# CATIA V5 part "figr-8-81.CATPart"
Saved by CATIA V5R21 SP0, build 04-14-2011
Part number: Part1
Bounding box of the stored display mesh (mm): x -52.625 to 52.625, y -77.625 to 77.625, z 0 to 30
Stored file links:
  D:\CATIA V5R21 E-RESOURCES\CATIA-V5R21\catia-v5r21-prt\c08-catia-v5r20-prt\c08-catia-v5r21-figr-8-81.CATPart
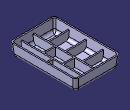
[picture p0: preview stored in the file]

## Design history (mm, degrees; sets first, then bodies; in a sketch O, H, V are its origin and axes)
Set1
  Plane1: type Offset, RefPlane xy-plane, Offset 30
  Plane2: type Offset, RefPlane face of Pad1, Offset -8, reversed
Body1 (main body)
  Sketch1 on xy-plane, origin (0, 0, 0), H (1, 0, 0), V (0, 1, 0)
    line L1 (-50, 75) -> (50, 75)
    line L2 (50, 75) -> (50, -75)
    line L3 (50, -75) -> (-50, -75)
    line L4 (-50, -75) -> (-50, 75)
    axis line L5 (50, -75) -> (-50, 75)
    length L3 = 100
    length L2 = 150
    horizontal: L1 H, L3 H
    vertical: L2 V, L4 V
    midpoint: O L5
  Pad1: profile Sketch1, direction (0, 0, 1), length 0, opposite side up to Plane1
  Draft1: Angle -5, Neutral face of Pad1, PullDir face of Pad1, SupportToDraft (face of Pad1; face of Pad1; face of Pad1; face of Pad1)
  Fillet1: radius 7, on edge [face of Pad1 | face of Pad1] (x4)
  Fillet2: radius 10, on edge [face of Pad1 | face of Pad1] (x4)
  Shell1: ExtOffset 0, Face face of Pad1, IntOffset 3
  Sketch2 on Plane2, origin (0, 0, 22), H (1, 0, 0), V (0, -1, 0)
    line L1 (28.1747, 54.0191) -> (28.1747, -59.2866)
    line L2 (0, 54.0191) -> (0, -59.2866)
    point P3 (0, 54.0191)
    line L3 (-9.5939, 0) -> (-33.0562, 0)
    point P5 (-9.5939, 0)
    line L4 (-9.5939, -40.4023) -> (-33.0562, -40.4023)
    point P7 (-9.5939, -40.4023)
    point P8 (-33.0562, -40.4023)
    point P9 (-33.0562, 40.4023)
    point P10 (-9.5939, 40.4023)
    line L5 (-9.5939, 40.4023) -> (-33.0562, 40.4023)
    line L6 (28.1747, 22.6983) -> (0, 22.6983)
    point P11 (28.1747, 22.6983)
    point P12 (0, 22.6983)
    point P13 (0, -22.6983)
    point P14 (28.1747, -22.6983)
    line L7 (28.1747, -22.6983) -> (0, -22.6983)
    line L8 (28.1747, 0) -> (41.8849, 0)
    point P15 (28.1747, 0)
    vertical: L1 V, L2 V
    coincidence: P3 V, P5 H, P11 L1, P12 L2, P15 L1, P15 H
    horizontal: L3 H, L4 H, L6 H, L8 H
    symmetry: P8 P9 L3, P7 P10 L3, L4 L5 L3, P12 P13 H, P11 P14 H, L6 L7 H
  Stiffener1: ExtendedProfile Sketch2, ThicknessTop 1, ThicknessValue 3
